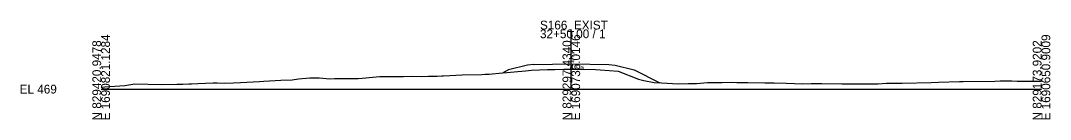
# Model space of a CAD drawing. Extents: x 1621104 to 1621433, y 1192880 to 1199414.
# Drawn here: x 1621104.2 to 1621432.7, y 1197879.5 to 1197911.2 of the extents above; entities that cross this region are included whole.
import ezdxf

# ---------------------------------------------------------------- set-up
doc = ezdxf.new("R2010")
doc.units = 0
for name, color, linetype in [('RD_GPK_XS_Cell', 7, 'Continuous'), ('RD_XS_EarthShd', 7, 'Continuous'), ('RD_XS_ExGround', 7, 'Continuous'), ('RD_XS_Pave', 7, 'Continuous'), ('RD_XS_TieSlope', 7, 'Continuous'), ('RD_XS_TX_Elev_EX', 7, 'Continuous'), ('RD_XS_TX_Elev_PR', 7, 'Continuous')]:
    doc.layers.add(name, color=color, linetype=linetype)

msp = doc.modelspace()

# ---------------------------------------------------------------- linework, layer by layer
at = {"layer": 'RD_GPK_XS_Cell'}
for p, q in [((1621279.86, 1197889.24), (1621279.86, 1197908.32)), ((1621129.86, 1197889.24), (1621279.86, 1197889.24)), ((1621279.86, 1197889.24), (1621429.86, 1197889.24))]:
    msp.add_line(p, q, dxfattribs=at)
at = {"layer": 'RD_XS_EarthShd'}
for p, q in [((1621267.86, 1197897.07), (1621265.86, 1197896.91)), ((1621291.86, 1197897.07), (1621293.86, 1197896.91))]:
    msp.add_line(p, q, dxfattribs=at)
at = {"layer": 'RD_XS_ExGround'}
msp.add_lwpolyline([(1621129.86, 1197889.87), (1621131.07, 1197889.92), (1621137.39, 1197890.45), (1621140.64, 1197890.93), (1621149.04, 1197890.71), (1621154.04, 1197890.83), (1621155.89, 1197890.87), (1621157.84, 1197890.92), (1621158.74, 1197890.92), (1621160.68, 1197891), (1621165.58, 1197891.2), (1621166.88, 1197891.23), (1621169.11, 1197891.18), (1621172.11, 1197891.24), (1621174.35, 1197891.31), (1621180.43, 1197891.66), (1621181.75, 1197891.78), (1621187.24, 1197892.08), (1621190.75, 1197892.22), (1621192.85, 1197892.52), (1621196.44, 1197892.87), (1621199.45, 1197892.81), (1621202.81, 1197892.56), (1621204.36, 1197892.59), (1621211.17, 1197892.64), (1621211.86, 1197892.68), (1621213.12, 1197892.79), (1621218.82, 1197893.25), (1621221.61, 1197893.28), (1621226.28, 1197893.29), (1621229.18, 1197893.34), (1621231.94, 1197893.32), (1621234.3, 1197893.39), (1621237.11, 1197893.42), (1621238.52, 1197893.46), (1621239.13, 1197893.51), (1621245.04, 1197893.84), (1621251.31, 1197893.96), (1621252.4, 1197894), (1621253.62, 1197894.06), (1621254.62, 1197894.08), (1621256.84, 1197894.39), (1621265.24, 1197895.1), (1621267.13, 1197895.28), (1621272.24, 1197895.48), (1621274.62, 1197895.56), (1621277.52, 1197895.58), (1621279.86, 1197895.59), (1621281.28, 1197895.6), (1621287.52, 1197895.5), (1621289.09, 1197895.4), (1621294.79, 1197894.99), (1621301.27, 1197892.39), (1621302.97, 1197892.01), (1621306.26, 1197891.38), (1621308.65, 1197891.23), (1621313.98, 1197890.91), (1621317.19, 1197891.09), (1621319.79, 1197891.05), (1621323.31, 1197891.31), (1621328, 1197891.37), (1621331.31, 1197891.42), (1621332.67, 1197891.38), (1621336.21, 1197891.33), (1621341.64, 1197891.28), (1621344.56, 1197891.27), (1621348.35, 1197891.19), (1621353.73, 1197890.95), (1621356.39, 1197891), (1621359.81, 1197891.06), (1621366.2, 1197890.91), (1621368.69, 1197890.9), (1621374.3, 1197890.94), (1621377.79, 1197890.92), (1621380.4, 1197891.12), (1621381.65, 1197891.1), (1621385.39, 1197891.19), (1621394.68, 1197891.36), (1621396.99, 1197891.45), (1621403.73, 1197891.63), (1621404.83, 1197891.66), (1621414.97, 1197891.75), (1621416.64, 1197891.9), (1621420.38, 1197891.91), (1621422.14, 1197891.81), (1621422.79, 1197891.81), (1621425.27, 1197891.78), (1621429.29, 1197891.8), (1621429.86, 1197891.82)], dxfattribs=at)
at = {"layer": 'RD_XS_Pave'}
for p, q in [((1621267.86, 1197897.07), (1621279.86, 1197897.31)), ((1621279.86, 1197897.31), (1621291.86, 1197897.07))]:
    msp.add_line(p, q, dxfattribs=at)
at = {"layer": 'RD_XS_TieSlope'}
for p, q in [((1621265.86, 1197896.91), (1621259.86, 1197895.41)), ((1621293.86, 1197896.91), (1621299.86, 1197895.41)), ((1621259.86, 1197895.41), (1621258.01, 1197894.49)), ((1621299.86, 1197895.41), (1621308.15, 1197891.26))]:
    msp.add_line(p, q, dxfattribs=at)

# ---------------------------------------------------------------- texts
at = {"layer": 'RD_GPK_XS_Cell'}
for s, p in [('S166_EXIST', (1621269.86, 1197908.32)), ('32+50.00 / 1', (1621269.86, 1197905.52)), ('EL 469', (1621103.86, 1197887.84))]:
    msp.add_text(s, height=2.8, dxfattribs=at).set_placement(p)
for s, p in [('E 1690821.1284', (1621132.66, 1197879.24)), ('E 1690736.0146', (1621282.66, 1197879.24)), ('E 1690650.9009', (1621432.66, 1197879.24)), ('N 829420.9478', (1621129.86, 1197879.24)), ('N 829297.4340', (1621279.86, 1197879.24)), ('N 829173.9202', (1621429.86, 1197879.24))]:
    msp.add_text(s, height=2.8, rotation=90, dxfattribs=at).set_placement(p)
at = {"layer": 'RD_XS_TX_Elev_EX'}
msp.add_text('475.36', height=1, dxfattribs=at).set_placement((1621279.76, 1197895.69))
at = {"layer": 'RD_XS_TX_Elev_PR'}
msp.add_text(' 477.07', height=1, rotation=90, dxfattribs=at).set_placement((1621280.86, 1197897.31))

doc.saveas('drawing.dxf')
